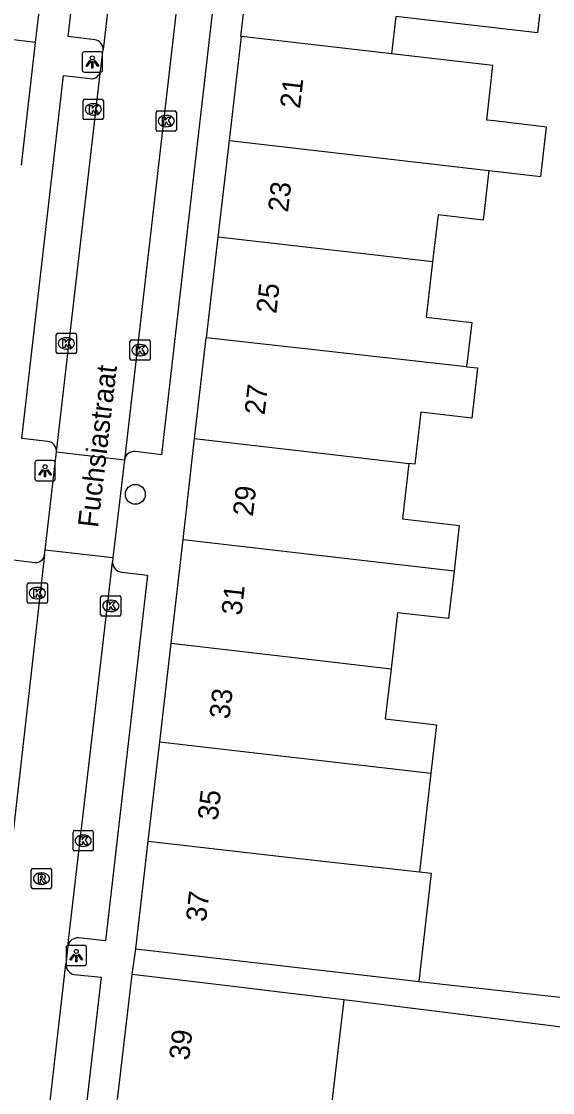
# Model space of a CAD drawing. Extents: x 161696 to 162377, y 380761 to 381673.
# Drawn here: x 161949.3 to 161975.5, y 381041 to 381093.8 of the extents above; entities that cross this region are included whole.
import ezdxf

# ---------------------------------------------------------------- set-up
doc = ezdxf.new("R2010")
doc.units = 0
for name, color, linetype in [('IMGEO_Boom', 7, 'Continuous'), ('IMGEO_Kolk', 7, 'Continuous'), ('IMGEO_Lichtpunt', 7, 'Continuous'), ('IMGEO_Openbare_ruimte_label', 7, 'Continuous'), ('IMGEO_Pand', 7, 'Continuous'), ('IMGEO_Pand_nummerreeks', 7, 'Continuous'), ('IMGEO_Rijbaan_lokaal_open', 7, 'Continuous'), ('IMGEO_Rioolput', 7, 'Continuous'), ('IMGEO_Voetpad_open', 7, 'Continuous')]:
    doc.layers.add(name, color=color, linetype=linetype)

msp = doc.modelspace()

# ---------------------------------------------------------------- linework, layer by layer
at = {"layer": 'IMGEO_Boom'}
msp.add_circle((161954.959, 381070.464), 0.489, dxfattribs=at)
at = {"layer": 'IMGEO_Kolk'}
for p, q in [((161952.385, 381089), (161952.385, 381089.852)), ((161952.46, 381089.926), (161953.312, 381089.926)), ((161953.386, 381089.852), (161953.386, 381089)), ((161952.873, 381089.706), (161952.898, 381089.706)), ((161955.981, 381088.426), (161955.981, 381089.278)), ((161956.056, 381089.352), (161956.908, 381089.352)), ((161956.982, 381089.278), (161956.982, 381088.426)), ((161953.312, 381088.926), (161952.46, 381088.926)), ((161952.896, 381089.146), (161952.871, 381089.146)), ((161956.469, 381089.132), (161956.494, 381089.132)), ((161956.908, 381088.352), (161956.056, 381088.352)), ((161956.492, 381088.572), (161956.467, 381088.572)), ((161951.061, 381077.473), (161951.061, 381078.325)), ((161951.136, 381078.399), (161951.988, 381078.399)), ((161952.062, 381078.325), (161952.062, 381077.473)), ((161951.549, 381078.179), (161951.574, 381078.179)), ((161954.692, 381077.141), (161954.692, 381077.993)), ((161954.767, 381078.067), (161955.619, 381078.067)), ((161955.18, 381077.847), (161955.205, 381077.847)), ((161955.693, 381077.993), (161955.693, 381077.141)), ((161951.988, 381077.399), (161951.136, 381077.399)), ((161951.572, 381077.619), (161951.547, 381077.619)), ((161955.203, 381077.287), (161955.178, 381077.287)), ((161955.619, 381077.067), (161954.767, 381077.067)), ((161949.705, 381066.097), (161950.557, 381066.097)), ((161949.63, 381065.171), (161949.63, 381066.023)), ((161950.118, 381065.877), (161950.143, 381065.877)), ((161950.631, 381066.023), (161950.631, 381065.171)), ((161950.557, 381065.097), (161949.705, 381065.097)), ((161950.141, 381065.317), (161950.116, 381065.317)), ((161953.25, 381064.544), (161953.25, 381065.396)), ((161953.325, 381065.47), (161954.177, 381065.47)), ((161953.738, 381065.25), (161953.763, 381065.25)), ((161954.251, 381065.396), (161954.251, 381064.544)), ((161954.177, 381064.47), (161953.325, 381064.47)), ((161953.761, 381064.69), (161953.736, 381064.69)), ((161951.889, 381052.975), (161951.889, 381053.827)), ((161951.964, 381053.901), (161952.816, 381053.901)), ((161952.377, 381053.681), (161952.402, 381053.681)), ((161952.89, 381053.827), (161952.89, 381052.975)), ((161952.816, 381052.901), (161951.964, 381052.901)), ((161952.4, 381053.121), (161952.375, 381053.121))]:
    msp.add_line(p, q, dxfattribs=at)
for points in [[(161952.385, 381089), (161952.385, 381089.852)], [(161952.46, 381089.926), (161953.312, 381089.926)], [(161953.386, 381089.852), (161953.386, 381089)], [(161952.706, 381089.626), (161952.829, 381089.626), (161952.829, 381089.475), (161952.959, 381089.626), (161953.123, 381089.626), (161952.977, 381089.475), (161953.13, 381089.226), (161952.978, 381089.226), (161952.893, 381089.39), (161952.829, 381089.323), (161952.829, 381089.226), (161952.706, 381089.226), (161952.706, 381089.626)], [(161955.981, 381088.426), (161955.981, 381089.278)], [(161956.056, 381089.352), (161956.908, 381089.352)], [(161956.982, 381089.278), (161956.982, 381088.426)], [(161953.312, 381088.926), (161952.46, 381088.926)], [(161956.302, 381089.052), (161956.425, 381089.052), (161956.425, 381088.901), (161956.555, 381089.052), (161956.719, 381089.052), (161956.573, 381088.901), (161956.726, 381088.652), (161956.574, 381088.652), (161956.489, 381088.816), (161956.425, 381088.749), (161956.425, 381088.652), (161956.302, 381088.652), (161956.302, 381089.052)], [(161956.908, 381088.352), (161956.056, 381088.352)], [(161951.061, 381077.473), (161951.061, 381078.325)], [(161951.136, 381078.399), (161951.988, 381078.399)], [(161952.062, 381078.325), (161952.062, 381077.473)], [(161951.382, 381078.099), (161951.505, 381078.099), (161951.505, 381077.948), (161951.635, 381078.099), (161951.799, 381078.099), (161951.653, 381077.948), (161951.806, 381077.699), (161951.654, 381077.699), (161951.569, 381077.863), (161951.505, 381077.796), (161951.505, 381077.699), (161951.382, 381077.699), (161951.382, 381078.099)], [(161954.692, 381077.141), (161954.692, 381077.993)], [(161954.767, 381078.067), (161955.619, 381078.067)], [(161955.013, 381077.767), (161955.136, 381077.767), (161955.136, 381077.616), (161955.266, 381077.767), (161955.43, 381077.767), (161955.284, 381077.616), (161955.437, 381077.367), (161955.285, 381077.367), (161955.2, 381077.531), (161955.136, 381077.464), (161955.136, 381077.367), (161955.013, 381077.367), (161955.013, 381077.767)], [(161955.693, 381077.993), (161955.693, 381077.141)], [(161951.988, 381077.399), (161951.136, 381077.399)], [(161955.619, 381077.067), (161954.767, 381077.067)], [(161949.705, 381066.097), (161950.557, 381066.097)], [(161949.63, 381065.171), (161949.63, 381066.023)], [(161949.951, 381065.797), (161950.074, 381065.797), (161950.074, 381065.646), (161950.204, 381065.797), (161950.368, 381065.797), (161950.222, 381065.646), (161950.375, 381065.397), (161950.223, 381065.397), (161950.138, 381065.561), (161950.074, 381065.494), (161950.074, 381065.397), (161949.951, 381065.397), (161949.951, 381065.797)], [(161950.631, 381066.023), (161950.631, 381065.171)], [(161950.557, 381065.097), (161949.705, 381065.097)], [(161953.25, 381064.544), (161953.25, 381065.396)], [(161953.325, 381065.47), (161954.177, 381065.47)], [(161953.571, 381065.17), (161953.694, 381065.17), (161953.694, 381065.019), (161953.824, 381065.17), (161953.988, 381065.17), (161953.842, 381065.019), (161953.995, 381064.77), (161953.843, 381064.77), (161953.758, 381064.934), (161953.694, 381064.867), (161953.694, 381064.77), (161953.571, 381064.77), (161953.571, 381065.17)], [(161954.251, 381065.396), (161954.251, 381064.544)], [(161954.177, 381064.47), (161953.325, 381064.47)], [(161951.889, 381052.975), (161951.889, 381053.827)], [(161951.964, 381053.901), (161952.816, 381053.901)], [(161952.21, 381053.601), (161952.333, 381053.601), (161952.333, 381053.45), (161952.463, 381053.601), (161952.627, 381053.601), (161952.481, 381053.45), (161952.634, 381053.201), (161952.482, 381053.201), (161952.397, 381053.365), (161952.333, 381053.298), (161952.333, 381053.201), (161952.21, 381053.201), (161952.21, 381053.601)], [(161952.89, 381053.827), (161952.89, 381052.975)], [(161952.816, 381052.901), (161951.964, 381052.901)]]:
    msp.add_lwpolyline(points, dxfattribs=at)
for centre, start, end in [((161952.462, 381089.85), 91.552, 178.448), ((161952.462, 381089.85), 91.552, 178.448), ((161953.31, 381089.85), 1.552, 88.448), ((161953.31, 381089.85), 1.552, 88.448), ((161956.058, 381089.276), 91.552, 178.448), ((161956.058, 381089.276), 91.552, 178.448), ((161956.906, 381089.276), 1.552, 88.448), ((161956.906, 381089.276), 1.552, 88.448), ((161952.462, 381089.002), 181.552, 268.448), ((161952.462, 381089.002), 181.552, 268.448), ((161953.31, 381089.002), 271.552, 358.448), ((161953.31, 381089.002), 271.552, 358.448), ((161956.058, 381088.428), 181.552, 268.448), ((161956.058, 381088.428), 181.552, 268.448), ((161956.906, 381088.428), 271.552, 358.448), ((161956.906, 381088.428), 271.552, 358.448), ((161951.138, 381078.323), 91.552, 178.448), ((161951.138, 381078.323), 91.552, 178.448), ((161951.986, 381078.323), 1.552, 88.448), ((161951.986, 381078.323), 1.552, 88.448), ((161954.769, 381077.991), 91.552, 178.448), ((161954.769, 381077.991), 91.552, 178.448), ((161955.617, 381077.991), 1.552, 88.448), ((161955.617, 381077.991), 1.552, 88.448), ((161951.138, 381077.475), 181.552, 268.448), ((161951.138, 381077.475), 181.552, 268.448), ((161951.986, 381077.475), 271.552, 358.448), ((161951.986, 381077.475), 271.552, 358.448), ((161954.769, 381077.143), 181.552, 268.448), ((161954.769, 381077.143), 181.552, 268.448), ((161955.617, 381077.143), 271.552, 358.448), ((161955.617, 381077.143), 271.552, 358.448), ((161949.707, 381066.021), 91.552, 178.448), ((161949.707, 381066.021), 91.552, 178.448), ((161950.555, 381066.021), 1.552, 88.448), ((161950.555, 381066.021), 1.552, 88.448), ((161949.707, 381065.173), 181.552, 268.448), ((161949.707, 381065.173), 181.552, 268.448), ((161950.555, 381065.173), 271.552, 358.448), ((161950.555, 381065.173), 271.552, 358.448), ((161953.327, 381065.394), 91.552, 178.448), ((161953.327, 381065.394), 91.552, 178.448), ((161954.175, 381065.394), 1.552, 88.448), ((161954.175, 381065.394), 1.552, 88.448), ((161953.327, 381064.546), 181.552, 268.448), ((161953.327, 381064.546), 181.552, 268.448), ((161954.175, 381064.546), 271.552, 358.448), ((161954.175, 381064.546), 271.552, 358.448), ((161951.966, 381053.825), 91.552, 178.448), ((161951.966, 381053.825), 91.552, 178.448), ((161952.814, 381053.825), 1.552, 88.448), ((161952.814, 381053.825), 1.552, 88.448), ((161951.966, 381052.977), 181.552, 268.448), ((161951.966, 381052.977), 181.552, 268.448), ((161952.814, 381052.977), 271.552, 358.448), ((161952.814, 381052.977), 271.552, 358.448)]:
    msp.add_arc(centre, 0.0765, start, end, dxfattribs=at)
for centre, major_axis, ratio, start_param, end_param in [((161952.872, 381089.426), (-0.387, 0.002), 0.722429, 4.712389, 7.853982), ((161952.897, 381089.426), (-0.39, 0.002), 0.717154, 1.570796, 4.712389), ((161956.468, 381088.852), (-0.387, 0.002), 0.722429, 4.712389, 7.853982), ((161956.493, 381088.852), (-0.39, 0.002), 0.717154, 1.570796, 4.712389), ((161951.548, 381077.899), (-0.387, 0.002), 0.722429, 4.712389, 7.853982), ((161951.573, 381077.899), (-0.39, 0.002), 0.717154, 1.570796, 4.712389), ((161955.179, 381077.567), (-0.387, 0.002), 0.722429, 4.712389, 7.853982), ((161955.204, 381077.567), (-0.39, 0.002), 0.717154, 1.570796, 4.712389), ((161950.117, 381065.597), (-0.387, 0.002), 0.722429, 4.712389, 7.853982), ((161950.142, 381065.597), (-0.39, 0.002), 0.717154, 1.570796, 4.712389), ((161953.737, 381064.97), (-0.387, 0.002), 0.722429, 4.712389, 7.853982), ((161953.762, 381064.97), (-0.39, 0.002), 0.717154, 1.570796, 4.712389), ((161952.376, 381053.401), (-0.387, 0.002), 0.722429, 4.712389, 7.853982), ((161952.401, 381053.401), (-0.39, 0.002), 0.717154, 1.570796, 4.712389)]:
    msp.add_ellipse(centre, major_axis=major_axis, ratio=ratio, start_param=start_param, end_param=end_param, dxfattribs=at)
at = {"layer": 'IMGEO_Lichtpunt'}
for p, q in [((161952.346, 381092.165), (161952.346, 381091.358)), ((161952.346, 381092.165), (161952.346, 381091.358)), ((161953.248, 381092.26), (161952.44, 381092.26)), ((161953.248, 381092.26), (161952.44, 381092.26)), ((161953.342, 381091.358), (161953.342, 381092.165)), ((161953.342, 381091.358), (161953.342, 381092.165)), ((161952.44, 381091.264), (161953.248, 381091.264)), ((161952.44, 381091.264), (161953.248, 381091.264)), ((161950.015, 381072.028), (161950.015, 381071.221)), ((161950.015, 381072.028), (161950.015, 381071.221)), ((161950.917, 381072.123), (161950.109, 381072.123)), ((161950.917, 381072.123), (161950.109, 381072.123)), ((161951.011, 381071.221), (161951.011, 381072.028)), ((161951.011, 381071.221), (161951.011, 381072.028)), ((161950.109, 381071.127), (161950.917, 381071.127)), ((161950.109, 381071.127), (161950.917, 381071.127)), ((161951.552, 381048.147), (161951.552, 381047.34)), ((161951.552, 381048.147), (161951.552, 381047.34)), ((161952.454, 381048.242), (161951.646, 381048.242)), ((161952.454, 381048.242), (161951.646, 381048.242)), ((161952.548, 381047.34), (161952.548, 381048.147)), ((161952.548, 381047.34), (161952.548, 381048.147)), ((161951.646, 381047.246), (161952.454, 381047.246)), ((161951.646, 381047.246), (161952.454, 381047.246))]:
    msp.add_line(p, q, dxfattribs=at)
for points in [[(161952.72, 381091.829), (161952.759, 381091.801), (161952.571, 381091.539), (161952.533, 381091.566), (161952.72, 381091.829)], [(161952.822, 381091.781), (161952.869, 381091.781), (161952.869, 381091.459), (161952.822, 381091.459), (161952.822, 381091.781)], [(161952.932, 381091.801), (161952.97, 381091.828), (161953.157, 381091.566), (161953.118, 381091.538), (161952.932, 381091.801)], [(161950.389, 381071.692), (161950.428, 381071.664), (161950.24, 381071.402), (161950.202, 381071.429), (161950.389, 381071.692)], [(161950.491, 381071.644), (161950.538, 381071.644), (161950.538, 381071.322), (161950.491, 381071.322), (161950.491, 381071.644)], [(161950.601, 381071.664), (161950.639, 381071.691), (161950.826, 381071.429), (161950.787, 381071.401), (161950.601, 381071.664)], [(161951.926, 381047.811), (161951.965, 381047.783), (161951.777, 381047.521), (161951.739, 381047.548), (161951.926, 381047.811)], [(161952.028, 381047.763), (161952.075, 381047.763), (161952.075, 381047.441), (161952.028, 381047.441), (161952.028, 381047.763)], [(161952.138, 381047.783), (161952.176, 381047.81), (161952.363, 381047.548), (161952.324, 381047.52), (161952.138, 381047.783)]]:
    msp.add_lwpolyline(points, dxfattribs=at)
for centre in [(161952.845, 381091.963), (161950.514, 381071.826), (161952.051, 381047.945)]:
    msp.add_circle(centre, 0.0994, dxfattribs=at)
for centre, start, end in [((161952.44, 381092.165), 90, 180), ((161952.44, 381092.165), 90, 180), ((161953.248, 381092.165), 0, 90), ((161953.248, 381092.165), 0, 90), ((161952.44, 381091.358), 180, 270), ((161952.44, 381091.358), 180, 270), ((161953.248, 381091.358), 270, 0), ((161953.248, 381091.358), 270, 360), ((161950.109, 381072.028), 90, 180), ((161950.109, 381072.028), 90, 180), ((161950.917, 381072.028), 0, 90), ((161950.917, 381072.028), 0, 90), ((161950.109, 381071.221), 180, 270), ((161950.109, 381071.221), 180, 270), ((161950.917, 381071.221), 270, 0), ((161950.917, 381071.221), 270, 360), ((161951.646, 381048.147), 90, 180), ((161951.646, 381048.147), 90, 180), ((161952.454, 381048.147), 0, 90), ((161952.454, 381048.147), 0, 90), ((161951.646, 381047.34), 180, 270), ((161951.646, 381047.34), 180, 270), ((161952.454, 381047.34), 270, 0), ((161952.454, 381047.34), 270, 360)]:
    msp.add_arc(centre, 0.0946, start, end, dxfattribs=at)
at = {"layer": 'IMGEO_Pand'}
for points in [[(161960.183, 381093.023), (161960.165, 381093.025), (161960.739, 381098.013)], [(161950.594, 381097.573), (161950.03, 381092.727)], [(161975.143, 381096.349), (161974.779, 381093.202), (161967.794, 381094.01), (161967.581, 381092.167)], [(161950.03, 381092.727), (161943.075, 381093.569), (161942.535, 381093.634), (161942.521, 381093.512)], [(161959.591, 381087.897), (161960.183, 381093.023)], [(161967.581, 381092.167), (161960.183, 381093.023)], [(161950.03, 381092.727), (161949.327, 381086.68)], [(161972.381, 381086.418), (161974.942, 381086.122), (161975.224, 381088.56), (161972.663, 381088.856), (161972.27, 381088.902), (161972.581, 381091.589), (161967.581, 381092.167)], [(161959.04, 381083.136), (161959.591, 381087.897)], [(161959.591, 381087.897), (161972.381, 381086.418)], [(161972.381, 381086.418), (161972.097, 381083.968), (161969.873, 381084.225), (161969.606, 381081.914)], [(161958.467, 381078.174), (161959.04, 381083.136)], [(161969.606, 381081.914), (161966.502, 381082.273), (161959.04, 381083.136)], [(161969.606, 381081.914), (161969.292, 381079.194), (161971.533, 381078.935), (161971.281, 381076.751)], [(161957.882, 381073.21), (161958.454, 381078.175), (161958.467, 381078.174)], [(161971.281, 381076.751), (161958.467, 381078.174)], [(161971.281, 381076.751), (161971.825, 381076.688), (161971.54, 381074.22), (161969.027, 381074.511), (161968.731, 381071.956), (161968.432, 381071.991)], [(161957.31, 381068.245), (161957.882, 381073.21)], [(161957.882, 381073.21), (161965.381, 381072.343), (161968.432, 381071.991)], [(161968.432, 381071.991), (161968.116, 381069.26), (161970.922, 381068.935), (161970.664, 381066.7)], [(161956.721, 381063.128), (161957.31, 381068.245)], [(161957.31, 381068.245), (161970.664, 381066.7)], [(161970.664, 381066.7), (161970.392, 381064.343), (161967.88, 381064.634), (161967.56, 381061.873)], [(161956.162, 381058.279), (161956.721, 381063.128)], [(161956.721, 381063.128), (161964.197, 381062.262), (161967.56, 381061.873)], [(161967.56, 381061.873), (161967.274, 381059.401), (161969.797, 381059.11), (161969.522, 381056.732)], [(161955.598, 381053.379), (161956.162, 381058.279)], [(161956.162, 381058.279), (161969.522, 381056.732)], [(161969.522, 381056.732), (161969.253, 381054.412), (161968.959, 381051.865)], [(161954.987, 381048.075), (161955.598, 381053.379)], [(161955.598, 381053.379), (161963.032, 381052.52), (161968.959, 381051.865)], [(161968.959, 381051.865), (161969.539, 381051.797), (161968.925, 381046.472)], [(161954.987, 381048.075), (161959.954, 381047.501), (161968.663, 381046.494), (161968.925, 381046.472)], [(161954.078, 381040.659), (161954.809, 381046.803)], [(161965.235, 381045.562), (161961.935, 381045.955), (161959.774, 381046.212), (161954.809, 381046.803)], [(161965.235, 381045.562), (161964.504, 381039.417), (161962.273, 381039.683)]]:
    msp.add_lwpolyline(points, dxfattribs=at)
at = {"layer": 'IMGEO_Rijbaan_lokaal_open'}
for points in [[(161956.44, 381118.843), (161953.377, 381092.373)], [(161957.495, 381098.83), (161954.427, 381072.168)], [(161953.25, 381091.329), (161953.377, 381092.373)], [(161951.073, 381072.558), (161953.25, 381091.329)], [(161950.519, 381067.711), (161951.073, 381072.558)], [(161951.073, 381072.558), (161954.427, 381072.168)], [(161954.427, 381072.168), (161953.854, 381067.335)], [(161950.49, 381067.484), (161950.519, 381067.711)], [(161953.854, 381067.335), (161950.519, 381067.711)], [(161950.49, 381067.484), (161948.346, 381048.6)], [(161951.635, 381048.212), (161953.839, 381067.124)], [(161953.854, 381067.335), (161953.839, 381067.124)], [(161951.635, 381048.212), (161951.537, 381047.312)], [(161948.215, 381018.454), (161951.537, 381047.312)]]:
    msp.add_lwpolyline(points, dxfattribs=at)
at = {"layer": 'IMGEO_Rioolput'}
for p, q in [((161949.834, 381051.109), (161949.834, 381051.961)), ((161949.909, 381052.035), (161950.761, 381052.035)), ((161950.322, 381051.815), (161950.347, 381051.815)), ((161950.835, 381051.961), (161950.835, 381051.109)), ((161950.761, 381051.035), (161949.909, 381051.035)), ((161950.345, 381051.255), (161950.32, 381051.255))]:
    msp.add_line(p, q, dxfattribs=at)
for points in [[(161949.834, 381051.109), (161949.834, 381051.961)], [(161949.909, 381052.035), (161950.761, 381052.035)], [(161950.835, 381051.961), (161950.835, 381051.109)], [(161950.423, 381051.733), (161950.171, 381051.735), (161950.171, 381051.335)], [(161950.171, 381051.335), (161950.295, 381051.335), (161950.295, 381051.497), (161950.306, 381051.497)], [(161950.349, 381051.654), (161950.295, 381051.654), (161950.295, 381051.573)], [(161950.295, 381051.573), (161950.347, 381051.573)], [(161950.353, 381051.468), (161950.424, 381051.335), (161950.564, 381051.335), (161950.499, 381051.461)], [(161950.761, 381051.035), (161949.909, 381051.035)]]:
    msp.add_lwpolyline(points, dxfattribs=at)
for centre, radius, start, end in [((161949.911, 381051.959), 0.0765, 91.552, 178.448), ((161949.911, 381051.959), 0.0765, 91.552, 178.448), ((161950.759, 381051.959), 0.0765, 1.552, 88.448), ((161950.759, 381051.959), 0.0765, 1.552, 88.448), ((161950.305, 381051.444), 0.0533, 26.0293, 88.6989), ((161950.331, 381051.762), 0.19, 274.7715, 282.9687), ((161950.355, 381051.558), 0.0964, 77.0061, 93.1865), ((161950.369, 381051.615), 0.0378, 276.6634, 79.6772), ((161950.422, 381051.623), 0.109, 350.3612, 89.416), ((161950.42, 381051.623), 0.112, 277.5842, 350.9817), ((161950.404, 381051.408), 0.108, 29.5134, 73.7905), ((161949.911, 381051.111), 0.0765, 181.552, 268.448), ((161949.911, 381051.111), 0.0765, 181.552, 268.448), ((161950.759, 381051.111), 0.0765, 271.552, 358.448), ((161950.759, 381051.111), 0.0765, 271.552, 358.448)]:
    msp.add_arc(centre, radius, start, end, dxfattribs=at)
for centre, major_axis, ratio, start_param, end_param in [((161950.321, 381051.535), (-0.387, 0.002), 0.722429, 4.712389, 7.853982), ((161950.346, 381051.535), (-0.39, 0.002), 0.717154, 1.570796, 4.712389)]:
    msp.add_ellipse(centre, major_axis=major_axis, ratio=ratio, start_param=start_param, end_param=end_param, dxfattribs=at)
at = {"layer": 'IMGEO_Voetpad_open'}
for points in [[(161952.964, 381092.857), (161951.645, 381093.013), (161954.632, 381118.68), (161955.997, 381118.513)], [(161957.923, 381098.345), (161959.211, 381098.169), (161956.248, 381072.413), (161954.968, 381072.575)], [(161950.641, 381073.073), (161949.367, 381073.221), (161951.427, 381091.091), (161952.741, 381090.942)], [(161947.955, 381049.089), (161946.607, 381049.227), (161948.676, 381067.266), (161950.017, 381067.113)], [(161954.291, 381066.622), (161955.561, 381066.474), (161953.485, 381048.466), (161952.154, 381048.613)], [(161954.809, 381046.803), (161954.987, 381048.075)], [(161951.94, 381046.805), (161953.271, 381046.679), (161950.997, 381026.968), (161949.716, 381016.912)], [(161968.925, 381046.472), (161977.976, 381045.458)], [(161980.281, 381031.865), (161981.587, 381043.512), (161965.235, 381045.562)]]:
    msp.add_lwpolyline(points, dxfattribs=at)
for centre, radius, start, end in [((161952.883, 381092.369), 0.494, 0.4059, 80.5428), ((161952.792, 381091.403), 0.464, 263.6985, 350.794), ((161950.591, 381072.592), 0.484, 355.956, 84.0262), ((161954.902, 381072.1), 0.479, 82.0442, 171.8648), ((161950.059, 381067.547), 0.436, 264.4712, 351.7469), ((161954.346, 381067.126), 0.507, 180.2259, 263.7738), ((161952.127, 381048.112), 0.502, 86.9051, 168.4771), ((161952.073, 381047.324), 0.536, 181.2952, 255.6652)]:
    msp.add_arc(centre, radius, start, end, dxfattribs=at)

# ---------------------------------------------------------------- texts
at = {"layer": 'IMGEO_Openbare_ruimte_label'}
msp.add_text('Fuchsiastraat', height=1, rotation=83.2801, dxfattribs=at).set_placement((161953.116, 381068.793))
at = {"layer": 'IMGEO_Pand_nummerreeks'}
for s, rotation, p in [('21', 83.4055, (161963.07, 381089.436)), ('23', 83.4055, (161962.48, 381084.329)), ('25', 83.4055, (161961.902, 381079.335)), ('27', 83.4055, (161961.325, 381074.342)), ('29', 83.4055, (161960.748, 381069.348)), ('31', 83.4054, (161960.183, 381064.468)), ('33', 83.4054, (161959.593, 381059.361)), ('35', 83.4054, (161959.016, 381054.367)), ('37', 83.4054, (161958.438, 381049.374)), ('39', 83.2111, (161957.607, 381042.555))]:
    msp.add_text(s, height=1, rotation=rotation, dxfattribs=at).set_placement(p)

doc.saveas('drawing.dxf')
